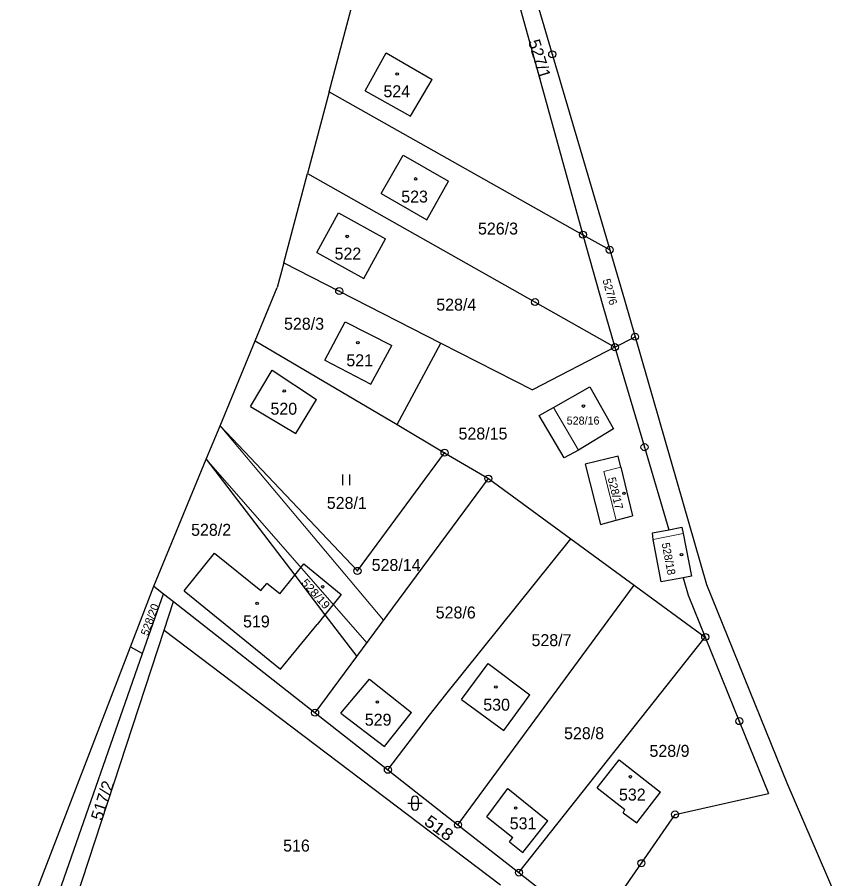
# Model space of a CAD drawing. Extents: x -633485 to -630509, y -1112692 to -1108818.
# Drawn here: x -633377.9 to -633261.7, y -1110685 to -1110562.6 of the extents above; entities that cross this region are included whole.
import ezdxf
from ezdxf.enums import TextEntityAlignment as Align

# ---------------------------------------------------------------- set-up
doc = ezdxf.new("R2010")
doc.units = 0
doc.header["$LTSCALE"] = 0.68
for name, color, linetype, lineweight in [('1', 7, 'Continuous', 25), ('13', 7, 'Continuous', 13), ('3', 7, 'Continuous', 25), ('4', 7, 'Continuous', 13), ('5', 7, 'Continuous', 25), ('8', 7, 'Continuous', 25)]:
    doc.layers.add(name, color=color, linetype=linetype, lineweight=lineweight)
doc.layers.add('2', color=7, linetype='Continuous')

msp = doc.modelspace()

# ---------------------------------------------------------------- linework, layer by layer
at = {"layer": '1'}
for p, q in [((-633316.94, -1110516.52), (-633301.83, -1110567.89)), ((-633333.55, -1110573.21), (-633324.71, -1110539.85)), ((-633311.39, -1110543.34), (-633304.83, -1110566.97)), ((-633328.42, -1110573.1), (-633325.43, -1110567.7)), ((-633325.43, -1110567.7), (-633318.87, -1110571.47)), ((-633304.83, -1110566.97), (-633297.46, -1110593.52)), ((-633301.83, -1110567.89), (-633293.66, -1110595.66)), ((-633321.98, -1110576.67), (-633318.87, -1110571.47)), ((-633333.55, -1110573.21), (-633336.63, -1110584.81)), ((-633333.55, -1110573.21), (-633297.46, -1110593.52)), ((-633328.42, -1110573.1), (-633321.98, -1110576.67)), ((-633326.15, -1110587.66), (-633323.02, -1110582.2)), ((-633323.02, -1110582.2), (-633316.56, -1110585.89)), ((-633339.99, -1110597.5), (-633336.63, -1110584.81)), ((-633336.63, -1110584.81), (-633304.27, -1110603.09)), ((-633319.66, -1110591.39), (-633316.56, -1110585.89)), ((-633326.15, -1110587.66), (-633319.66, -1110591.39)), ((-633335.29, -1110596.03), (-633332.19, -1110590.43)), ((-633332.19, -1110590.43), (-633325.52, -1110594.13)), ((-633328.6, -1110599.73), (-633325.52, -1110594.13)), ((-633297.46, -1110593.52), (-633294.65, -1110603.63)), ((-633297.46, -1110593.52), (-633293.66, -1110595.66)), ((-633293.66, -1110595.66), (-633291.56, -1110602.79)), ((-633335.29, -1110596.03), (-633328.6, -1110599.73)), ((-633339.99, -1110597.5), (-633340.93, -1110601.03)), ((-633339.99, -1110597.5), (-633332.11, -1110601.53)), ((-633344.05, -1110608.59), (-633340.93, -1110601.03)), ((-633332.11, -1110601.53), (-633317.65, -1110608.92)), ((-633304.27, -1110603.09), (-633292.91, -1110609.5)), ((-633291.56, -1110602.79), (-633290.05, -1110608.02)), ((-633294.65, -1110603.63), (-633292.91, -1110609.5)), ((-633334.13, -1110611.35), (-633331.27, -1110605.88)), ((-633331.27, -1110605.88), (-633324.65, -1110609.26)), ((-633292.91, -1110609.5), (-633290.05, -1110608.02)), ((-633290.05, -1110608.02), (-633279.88, -1110643.21)), ((-633349.04, -1110620.67), (-633344.05, -1110608.59)), ((-633344.05, -1110608.59), (-633323.89, -1110620.5)), ((-633327.61, -1110614.75), (-633324.65, -1110609.26)), ((-633323.89, -1110620.5), (-633317.65, -1110608.92)), ((-633317.65, -1110608.92), (-633304.63, -1110615.57)), ((-633292.91, -1110609.5), (-633304.63, -1110615.57)), ((-633292.91, -1110609.5), (-633288.71, -1110623.71)), ((-633334.13, -1110611.35), (-633327.61, -1110614.75)), ((-633344.74, -1110617.91), (-633341.62, -1110612.76)), ((-633341.62, -1110612.76), (-633335.35, -1110616.95)), ((-633301.64, -1110618.07), (-633296.5, -1110615.14)), ((-633296.5, -1110615.14), (-633293.1, -1110621.11)), ((-633344.74, -1110617.91), (-633338.27, -1110621.78)), ((-633338.27, -1110621.78), (-633335.35, -1110616.95)), ((-633303.66, -1110619.22), (-633301.64, -1110618.07)), ((-633300.14, -1110625.25), (-633303.66, -1110619.22)), ((-633351.01, -1110625.43), (-633349.04, -1110620.67)), ((-633323.89, -1110620.5), (-633317.13, -1110624.5)), ((-633293.1, -1110621.11), (-633298.1, -1110624.12)), ((-633288.71, -1110623.71), (-633285.24, -1110635.44)), ((-633317.13, -1110624.5), (-633310.9, -1110628.18)), ((-633298.1, -1110624.12), (-633300.14, -1110625.25)), ((-633292.46, -1110624.99), (-633297.15, -1110626.12)), ((-633292.08, -1110626.57), (-633292.46, -1110624.99)), ((-633358.46, -1110643.47), (-633351.01, -1110625.43)), ((-633351.01, -1110625.43), (-633338.43, -1110641.9)), ((-633297.15, -1110626.12), (-633294.95, -1110634.71)), ((-633292.08, -1110626.57), (-633290.41, -1110633.46)), ((-633329.61, -1110653.44), (-633310.9, -1110628.18)), ((-633310.9, -1110628.18), (-633299.18, -1110636.74)), ((-633292.72, -1110634.1), (-633290.41, -1110633.46)), ((-633294.95, -1110634.71), (-633292.72, -1110634.1)), ((-633285.24, -1110635.44), (-633283.39, -1110635.1)), ((-633283.39, -1110635.1), (-633283.22, -1110635.97)), ((-633287.59, -1110635.87), (-633285.24, -1110635.44)), ((-633287.46, -1110636.84), (-633287.59, -1110635.87)), ((-633283.22, -1110635.97), (-633282.05, -1110642.03)), ((-633316.94, -1110658.84), (-633299.18, -1110636.74)), ((-633299.18, -1110636.74), (-633290.18, -1110643.31)), ((-633286.36, -1110642.86), (-633287.46, -1110636.84)), ((-633354.14, -1110644.14), (-633349.84, -1110638.76)), ((-633349.84, -1110638.76), (-633343.25, -1110644.06)), ((-633283.22, -1110642.26), (-633286.36, -1110642.86)), ((-633282.05, -1110642.03), (-633283.22, -1110642.26)), ((-633283.22, -1110642.26), (-633282.49, -1110644.74)), ((-633361.78, -1110652.1), (-633358.46, -1110643.47)), ((-633358.46, -1110643.47), (-633357.09, -1110644.54)), ((-633343.25, -1110644.06), (-633342.41, -1110643.07)), ((-633340.56, -1110644.57), (-633342.41, -1110643.07)), ((-633315.23, -1110677.36), (-633290.18, -1110643.31)), ((-633290.18, -1110643.31), (-633280.08, -1110650.69)), ((-633279.88, -1110643.21), (-633268.46, -1110671.42)), ((-633360.09, -1110653.04), (-633357.09, -1110644.54)), ((-633357.09, -1110644.54), (-633355.65, -1110645.66)), ((-633354.14, -1110644.14), (-633340.47, -1110655.26)), ((-633282.49, -1110644.74), (-633280.08, -1110650.69)), ((-633356.98, -1110649.71), (-633355.65, -1110645.66)), ((-633355.65, -1110645.66), (-633335.53, -1110661.44)), ((-633334.13, -1110647.52), (-633335.24, -1110648.9)), ((-633334.13, -1110647.52), (-633329.61, -1110653.44)), ((-633372.08, -1110695.76), (-633356.98, -1110649.71)), ((-633356.98, -1110649.71), (-633309.16, -1110685.92)), ((-633340.47, -1110655.26), (-633335.24, -1110648.9)), ((-633306.56, -1110684.16), (-633280.08, -1110650.69)), ((-633280.08, -1110650.69), (-633275.23, -1110662.64)), ((-633377.88, -1110693.9), (-633361.78, -1110652.1)), ((-633361.78, -1110652.1), (-633360.09, -1110653.04)), ((-633374.72, -1110694.91), (-633360.09, -1110653.04)), ((-633335.53, -1110661.44), (-633329.61, -1110653.44)), ((-633314.71, -1110659.57), (-633310.91, -1110654.47)), ((-633310.91, -1110654.47), (-633305.01, -1110658.91)), ((-633331.9, -1110661.49), (-633327.78, -1110656.66)), ((-633327.78, -1110656.66), (-633321.84, -1110661.43)), ((-633319.28, -1110661.81), (-633316.94, -1110658.84)), ((-633314.71, -1110659.57), (-633308.7, -1110663.96)), ((-633308.7, -1110663.96), (-633305.01, -1110658.91)), ((-633335.53, -1110661.44), (-633325.19, -1110669.55)), ((-633331.9, -1110661.49), (-633325.69, -1110666.25)), ((-633325.69, -1110666.25), (-633321.84, -1110661.43)), ((-633325.19, -1110669.55), (-633319.28, -1110661.81)), ((-633275.23, -1110662.64), (-633271.06, -1110672.94)), ((-633295.43, -1110672.14), (-633292.31, -1110668.15)), ((-633292.31, -1110668.15), (-633286.43, -1110672.74)), ((-633325.19, -1110669.55), (-633315.23, -1110677.36)), ((-633268.46, -1110671.42), (-633261.66, -1110687.22)), ((-633311.12, -1110676.24), (-633308.15, -1110672.23)), ((-633308.15, -1110672.23), (-633302.43, -1110676.82)), ((-633295.43, -1110672.14), (-633291.5, -1110675.21)), ((-633289.78, -1110677.1), (-633286.43, -1110672.74)), ((-633284.37, -1110675.9), (-633271.06, -1110672.94)), ((-633291.76, -1110675.65), (-633291.5, -1110675.21)), ((-633311.12, -1110676.24), (-633307.44, -1110679.17)), ((-633291.76, -1110675.65), (-633289.78, -1110677.1)), ((-633289.15, -1110682.83), (-633284.37, -1110675.9)), ((-633315.23, -1110677.36), (-633306.56, -1110684.16)), ((-633306.01, -1110681.29), (-633302.43, -1110676.82)), ((-633307.91, -1110679.77), (-633307.44, -1110679.17)), ((-633307.91, -1110679.77), (-633306.01, -1110681.29)), ((-633295.86, -1110692.55), (-633289.15, -1110682.83)), ((-633306.56, -1110684.16), (-633295.86, -1110692.55))]:
    msp.add_line(p, q, dxfattribs=at)
for points in [[(-633349.04, -1110620.67), (-633329.51, -1110641.29), (-633317.13, -1110624.5)], [(-633338.43, -1110641.9), (-633337.16, -1110640.3), (-633331.81, -1110644.65), (-633334.13, -1110647.52)], [(-633340.56, -1110644.57), (-633338.43, -1110641.9), (-633334.13, -1110647.52)]]:
    msp.add_lwpolyline(points, dxfattribs=at)
at = {"layer": '13'}
msp.add_lwpolyline([(-633349.04, -1110620.67), (-633351.01, -1110625.43), (-633328.19, -1110651.53), (-633325.8, -1110648.31)], close=True, dxfattribs=at)
at = {"layer": '3'}
for p, q in [((-633331.601, -1110629.11), (-633331.601, -1110627.61)), ((-633330.6, -1110629.11), (-633330.6, -1110627.61)), ((-633322.331, -1110674.291), (-633320.329, -1110674.291)), ((-633321.831, -1110673.791), (-633321.831, -1110674.792)), ((-633320.829, -1110674.792), (-633320.829, -1110673.791))]:
    msp.add_line(p, q, dxfattribs=at)
for centre, start, end in [((-633321.33, -1110673.7909), 0, 180), ((-633321.33, -1110674.7909), 180, 359.98789)]:
    msp.add_arc(centre, 0.5, start, end, dxfattribs=at)
at = {"layer": '4'}
for p, q in [((-633301.64, -1110618.07), (-633298.1, -1110624.12)), ((-633292.08, -1110626.57), (-633294.48, -1110627.17)), ((-633294.48, -1110627.17), (-633292.72, -1110634.1)), ((-633287.46, -1110636.84), (-633283.22, -1110635.97))]:
    msp.add_line(p, q, dxfattribs=at)
at = {"layer": '5'}
for centre in [(-633323.8668, -1110570.6892), (-633321.2468, -1110585.5892), (-633330.9768, -1110593.7692), (-633329.4568, -1110608.8492), (-633339.9268, -1110615.7192), (-633297.3868, -1110617.8792), (-633291.6368, -1110630.2592), (-633283.4468, -1110638.9892), (-633334.4468, -1110643.5492), (-633343.7768, -1110645.8892), (-633309.8468, -1110657.7892), (-633326.6768, -1110659.9092), (-633290.7168, -1110670.5492), (-633307.0368, -1110674.9892)]:
    msp.add_circle(centre, 0.175, dxfattribs=at)
at = {"layer": '8'}
for centre, radius in [((-633301.83, -1110567.8899), 0.5), ((-633301.83, -1110567.8899), 0.0303), ((-633297.46, -1110593.5199), 0.5), ((-633297.46, -1110593.5199), 0.0303), ((-633293.66, -1110595.6599), 0.5), ((-633293.66, -1110595.6599), 0.0303), ((-633332.11, -1110601.5299), 0.5), ((-633332.11, -1110601.5299), 0.0303), ((-633304.27, -1110603.0899), 0.5), ((-633304.27, -1110603.0899), 0.0303), ((-633290.05, -1110608.0199), 0.5), ((-633290.05, -1110608.0199), 0.0303), ((-633292.91, -1110609.4999), 0.5), ((-633292.91, -1110609.4999), 0.0303), ((-633317.13, -1110624.4999), 0.5), ((-633288.71, -1110623.7099), 0.5), ((-633288.71, -1110623.7099), 0.0303), ((-633317.13, -1110624.4999), 0.0303), ((-633310.9, -1110628.1799), 0.5), ((-633310.9, -1110628.1799), 0.0303), ((-633329.51, -1110641.2899), 0.5), ((-633329.51, -1110641.2899), 0.0303), ((-633280.08, -1110650.6899), 0.5), ((-633280.08, -1110650.6899), 0.0303), ((-633335.53, -1110661.4399), 0.5), ((-633335.53, -1110661.4399), 0.0303), ((-633275.23, -1110662.6399), 0.5), ((-633275.23, -1110662.6399), 0.0303), ((-633325.19, -1110669.5499), 0.5), ((-633325.19, -1110669.5499), 0.0303), ((-633284.37, -1110675.8999), 0.5), ((-633284.37, -1110675.8999), 0.0303), ((-633315.23, -1110677.3599), 0.5), ((-633315.23, -1110677.3599), 0.0303), ((-633289.15, -1110682.8299), 0.5), ((-633289.15, -1110682.8299), 0.0303), ((-633306.56, -1110684.1599), 0.5), ((-633306.56, -1110684.1599), 0.0303)]:
    msp.add_circle(centre, radius, dxfattribs=at)

# ---------------------------------------------------------------- texts
at = {"layer": '2'}
for s, rotation, p in [('527/1', 287, (-633305.266, -1110566.074)), ('517/2', 72, (-633365.845, -1110676.881))]:
    msp.add_text(s, height=1.7, rotation=rotation, dxfattribs=at).set_placement(p)
for s, p in [('524', (-633325.82, -1110573.985)), ('523', (-633323.29, -1110588.955)), ('526/3', (-633312.38, -1110593.495)), ('522', (-633332.77, -1110597.055)), ('528/4', (-633318.31, -1110604.305)), ('528/3', (-633339.95, -1110607.025)), ('521', (-633331.09, -1110612.215)), ('520', (-633341.88, -1110619.095)), ('528/1', (-633333.87, -1110632.485)), ('528/2', (-633353.16, -1110636.305)), ('528/6', (-633318.39, -1110648.055)), ('528/7', (-633304.77, -1110651.985)), ('530', (-633311.63, -1110661.155)), ('529', (-633328.47, -1110663.285)), ('528/8', (-633300.14, -1110665.205)), ('528/9', (-633288, -1110667.715)), ('532', (-633292.34, -1110673.925)), ('531', (-633307.87, -1110678.015)), ('516', (-633340.08, -1110681.175))]:
    msp.add_text(s, height=1.7, dxfattribs=at).set_placement(p)
for s, height, rotation, p in [('527/6', 1.14, 286, (-633294.1739, -1110601.7959)), ('528/17', 1.14, 284, (-633293.386, -1110630.3981)), ('528/18', 1.14, 281, (-633285.8327, -1110639.6792)), ('528/20', 1.139, 70, (-633358.4957, -1110648.4048))]:
    msp.add_text(s, height=height, rotation=rotation, dxfattribs=at).set_placement(p, align=Align.CENTER)
for s, height, p in [('528/16', 1.14, (-633297.439, -1110620.5)), ('528/15', 1.7, (-633311.67, -1110622.622)), ('528/14', 1.7, (-633324.02, -1110641.305)), ('519', 1.7, (-633343.879, -1110649.325))]:
    msp.add_text(s, height=height, dxfattribs=at).set_placement(p, align=Align.CENTER)
at = {"layer": '2', "width": 1.1}
msp.add_text('528/19', height=1.139, rotation=312, dxfattribs=at).set_placement((-633335.8663, -1110644.9439), align=Align.CENTER)
at = {"layer": '2', "width": 1.15}
msp.add_text('518', height=1.7, rotation=324, dxfattribs=at).set_placement((-633320.179, -1110677.233))

doc.saveas('drawing.dxf')
